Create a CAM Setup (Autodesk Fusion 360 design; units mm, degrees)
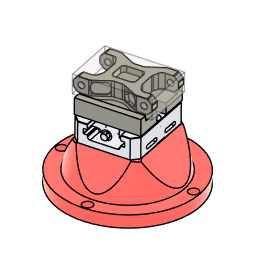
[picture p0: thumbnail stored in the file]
base_feature "Base Feature1"
base_feature "Base Feature1"
base_feature "Base Feature1"
base_feature "Base Feature1"
base_feature "Base Feature1"
as_built_joint "As-built1"
base_feature "Base Feature1"
step "RemoveFeatures"
sketch "Sketch1" plane through (0, 0, 0) normal (0, -1, 0) x axis (1, 0, 0)
  line L1 (35.56, 14.3539) -> (35.56, -14.3539)
  line L2 (40.4984, 27.6214) -> (36.4357, 18.4803)
  line L3 (65.1784, 33.655) -> (49.7827, 33.655)
  line L4 (65.1784, 49.53) -> (65.1784, 33.655)
  line L5 (45.4213, 49.53) -> (65.1784, 49.53)
  line L6 (12.4153, 32.9644) -> (41.2066, 48.4674)
  line L7 (-7.5985, 31.75) -> (7.5985, 31.75)
  line L8 (-41.2066, 48.4674) -> (-12.4153, 32.9644)
  line L9 (-65.1784, 49.53) -> (-45.4213, 49.53)
  line L10 (-65.1784, 33.655) -> (-65.1784, 49.53)
  line L11 (-49.7827, 33.655) -> (-65.1784, 33.655)
  line L12 (-36.4357, 18.4803) -> (-40.4984, 27.6214)
  line L13 (-35.56, -14.3539) -> (-35.56, 14.3539)
  line L14 (-40.4984, -27.6214) -> (-36.4357, -18.4803)
  line L15 (-65.1784, -33.655) -> (-49.7827, -33.655)
  line L16 (-65.1784, -49.53) -> (-65.1784, -33.655)
  line L17 (-45.4213, -49.53) -> (-65.1784, -49.53)
  line L18 (-12.4153, -32.9644) -> (-41.2066, -48.4674)
  line L19 (7.5985, -31.75) -> (-7.5985, -31.75)
  line L20 (41.2066, -48.4674) -> (12.4153, -32.9644)
  line L21 (65.1784, -49.53) -> (45.4213, -49.53)
  line L22 (65.1784, -33.655) -> (65.1784, -49.53)
  line L23 (49.7827, -33.655) -> (65.1784, -33.655)
  line L24 (36.4357, -18.4803) -> (40.4984, -27.6214)
  line L25 (-12.7, -12.7) -> (12.7, -12.7)
  line L26 (-12.7, 12.7) -> (-12.7, -12.7)
  line L27 (12.7, 12.7) -> (-12.7, 12.7)
  line L28 (12.7, -12.7) -> (12.7, 12.7)
  line L29 (-12.7, 12.7) -> (12.7, -12.7)
  line L30 (12.7, 12.7) -> (-12.7, -12.7)
  arc A1 centre (45.72, 14.3539) radius 10.16 clockwise from (35.56, 14.3539) to (36.4357, 18.4803)
  arc A2 centre (49.7827, 23.495) radius 10.16 clockwise from (40.4984, 27.6214) to (49.7827, 33.655)
  arc A3 centre (45.4213, 40.64) radius 8.89 clockwise from (41.2066, 48.4674) to (45.4213, 49.53)
  arc A4 centre (7.5985, 41.91) radius 10.16 clockwise from (12.4153, 32.9644) to (7.5985, 31.75)
  arc A5 centre (-7.5985, 41.91) radius 10.16 clockwise from (-7.5985, 31.75) to (-12.4153, 32.9644)
  arc A6 centre (-45.4213, 40.64) radius 8.89 clockwise from (-45.4213, 49.53) to (-41.2066, 48.4674)
  arc A7 centre (-49.7827, 23.495) radius 10.16 clockwise from (-49.7827, 33.655) to (-40.4984, 27.6214)
  arc A8 centre (-45.72, 14.3539) radius 10.16 clockwise from (-36.4357, 18.4803) to (-35.56, 14.3539)
  arc A9 centre (-45.72, -14.3539) radius 10.16 clockwise from (-35.56, -14.3539) to (-36.4357, -18.4803)
  arc A10 centre (-49.7827, -23.495) radius 10.16 clockwise from (-40.4984, -27.6214) to (-49.7827, -33.655)
  arc A11 centre (-45.4213, -40.64) radius 8.89 clockwise from (-41.2066, -48.4674) to (-45.4213, -49.53)
  arc A12 centre (-7.5985, -41.91) radius 10.16 clockwise from (-12.4153, -32.9644) to (-7.5985, -31.75)
  arc A13 centre (7.5985, -41.91) radius 10.16 clockwise from (7.5985, -31.75) to (12.4153, -32.9644)
  arc A14 centre (45.4213, -40.64) radius 8.89 clockwise from (45.4213, -49.53) to (41.2066, -48.4674)
  arc A15 centre (49.7827, -23.495) radius 10.16 clockwise from (49.7827, -33.655) to (40.4984, -27.6214)
  arc A16 centre (45.72, -14.3539) radius 10.16 clockwise from (36.4357, -18.4803) to (35.56, -14.3539)
  point P62 (0, 0)
  point P1 (0, 0)
  point P60 (-12.7, 12.7)
  point P61 (12.7, 12.7)
  point P59 (-12.7, -12.7)
  horizontal L25
  perpendicular L25 L26
  parallel L25 L27
  parallel L26 L28
  coincident L29 P62
  coincident L30 P62
  coincident P1 P62
  dimension "d1" distance P60 P61 = 25.4
  dimension "d2" distance P59 P60 = 25.4
extrude "Extrude1" cut sketch "Sketch1" profile of L25 L26 L27 L28 against normal blind 3.175
sketch "Sketch2" plane through (0, 0, 0) normal (0, 1, 0) x axis (1, 0, 0)
  line L1 (76.2, 50.8) -> (-76.2, 50.8)
  line L2 (76.2, -50.8) -> (76.2, 50.8)
  line L3 (-76.2, -50.8) -> (76.2, -50.8)
  line L4 (-76.2, 50.8) -> (-76.2, -50.8)
  line L5 (76.2, -50.8) -> (-76.2, 50.8)
  line L6 (-76.2, -50.8) -> (76.2, 50.8)
  point P6 (0, 0)
  point P1 (0, 0)
  point P4 (76.2, -50.8)
  point P5 (-76.2, -50.8)
  point P3 (76.2, 50.8)
  horizontal L1
  perpendicular L1 L2
  parallel L1 L3
  parallel L2 L4
  coincident L5 P6
  coincident L6 P6
  coincident P1 P6
  dimension "d5" distance P4 P5 = 152.4
  dimension "d6" distance P3 P4 = 101.6
extrude "Extrude2" new body sketch "Sketch2" profile of L1 L2 L3 L4 along normal blind 31.75 and against normal blind 6.35 bodies "Stock"
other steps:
create_component "CreateComponent1"
create_component "CreateComponent1"
create_component "CreateComponent2"
create_component "CreateComponent3"
create_component "CreateComponent4"
create_component "CreateComponent5"
create_component "CreateComponent2"
named bodies: "Stock"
